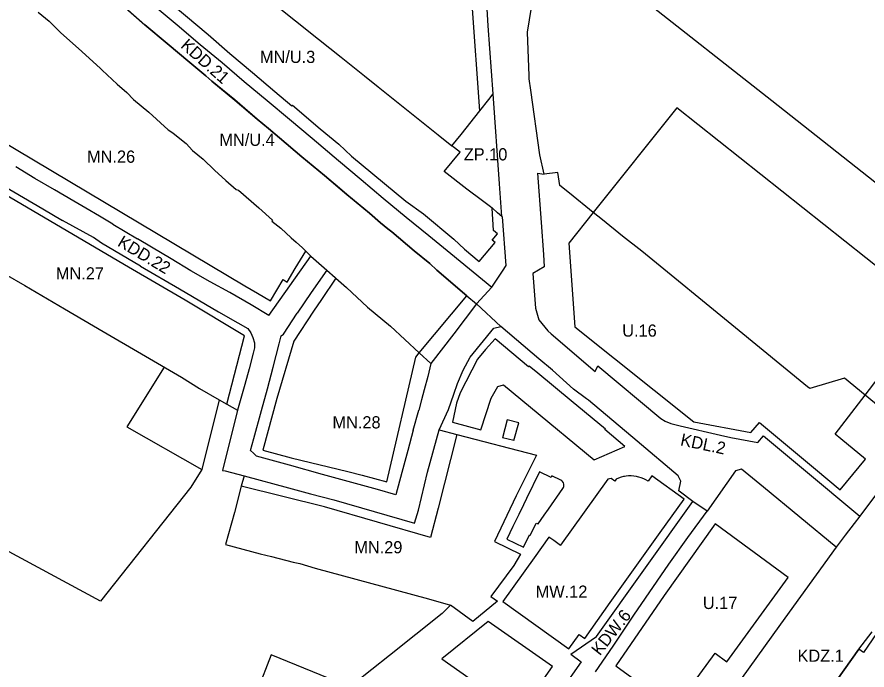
# Model space of a CAD drawing. Extents: x 7425067 to 7426806, y 5549054 to 5550619.
# Drawn here: x 7426010.9 to 7426359, y 5549627.2 to 5549894.6 of the extents above; entities that cross this region are included whole.
import ezdxf

# ---------------------------------------------------------------- set-up
doc = ezdxf.new("R2010")
doc.units = 0
for name, color, linetype in [('LIN_Linia Zabudowy Nieprzekraczalna', 7, 'Continuous'), ('LIN_linia zabudowy obowiązująca', 7, 'Continuous'), ('LIN_linie_rozgraniczajace', 7, 'Continuous'), ('TXT_Oznaczenia_przeznaczen', 7, 'Continuous')]:
    doc.layers.add(name, color=color, linetype=linetype)

msp = doc.modelspace()

# ---------------------------------------------------------------- linework, layer by layer
at = {"layer": 'LIN_Linia Zabudowy Nieprzekraczalna'}
for points in [[(7426200.381, 5549856.1483), (7426197.2527, 5549899.9387)], [(7425985.5251, 5549854.844), (7425996.26, 5549848.76), (7426104.12, 5549784.6), (7426109.41, 5549781.49), (7426114.72, 5549778.36), (7426119.83, 5549787.08), (7426121.57, 5549786.02), (7426124.86, 5549791.65), (7426129.1728, 5549798.7414)], [(7426104.0355, 5549764.0477), (7426079.76, 5549778.72), (7426056.48, 5549792.16), (7426008.48, 5549820.45), (7425975.3407, 5549839.5758)], [(7426200.17, 5549794.45), (7426206.73, 5549802.26), (7426205.5, 5549803.28), (7426207.65, 5549805.84), (7426206.0238, 5549807.2008), (7426205.4248, 5549816.3958)], [(7426129.1728, 5549798.7414), (7426131.18, 5549796.71), (7426136.68, 5549791.87), (7426137.71, 5549790.96), (7426141.23, 5549787.89), (7426141.5092, 5549787.6438), (7426135.63, 5549779), (7426132.35, 5549774.1), (7426124.1921, 5549761.9129)], [(7426096.874, 5549736.0834), (7426104.0355, 5549764.0477)], [(7426124.1921, 5549761.9129), (7426117.32, 5549738.38), (7426111.5641, 5549717.2208)], [(7426162.3022, 5549704.3065), (7426174.1872, 5549755.359), (7426175.6236, 5549757.0814)], [(7426071.1409, 5549751.2426), (7426055.9087, 5549726.8223), (7426086.61, 5549709.3037)], [(7426191.0178, 5549723.619), (7426183.33, 5549693.47), (7426180.274, 5549681.4855)], [(7426111.5641, 5549717.2208), (7426123.12, 5549714.13), (7426146.34, 5549708.54), (7426152.21, 5549706.94), (7426162.3022, 5549704.3065)], [(7426284.14, 5549697.19), (7426270.93, 5549706.67), (7426269.39, 5549704.52), (7426268.48, 5549705.06), (7426267.54, 5549705.53), (7426266.56, 5549705.92), (7426265.55, 5549706.23), (7426265.07, 5549706.35), (7426264.53, 5549706.46), (7426263.48, 5549706.62), (7426262.46, 5549706.69), (7426261.38, 5549706.67), (7426260.33, 5549706.57), (7426259.63, 5549706.46), (7426259.29, 5549706.4), (7426258.27, 5549706.14), (7426257.27, 5549705.8), (7426256.3, 5549705.38), (7426255.74, 5549704.59), (7426254.24, 5549705.67), (7426252.85, 5549705.41), (7426233.49, 5549678.3), (7426233.46, 5549678.26), (7426230.77, 5549680.19), (7426228.74, 5549681.63), (7426222.64, 5549673.08), (7426209.91, 5549655.22), (7426236.92, 5549635.84), (7426241.17, 5549641.77), (7426243.41, 5549640.17), (7426253.86, 5549654.81), (7426274.35, 5549683.48), (7426284.14, 5549697.19)], [(7426136.83, 5549694.02), (7426102.7507, 5549702.5468)], [(7426180.274, 5549681.4855), (7426136.83, 5549694.02)], [(7426296.746, 5549687.118), (7426275.9371, 5549657.7273)], [(7426326.69, 5549665.13), (7426296.746, 5549687.118)], [(7426275.9371, 5549657.7273), (7426256.0787, 5549628.8601)], [(7426370.03, 5549652.54), (7426362.92, 5549642.18), (7426357.542, 5549634.3437)], [(7426357.542, 5549634.3437), (7426355.61, 5549635.73), (7426346.69, 5549623.04), (7426339.9401, 5549613.4599)], [(7426256.0787, 5549628.8601), (7426270.22, 5549618.64), (7426280.1535, 5549611.3656)]]:
    msp.add_lwpolyline(points, dxfattribs=at)
at = {"layer": 'LIN_linia zabudowy obowiązująca'}
for points in [[(7426032.1248, 5549939.0592), (7426039.09, 5549932.41), (7426038.69, 5549931.97), (7426039.33, 5549931.35), (7426039.76, 5549931.8), (7426044.26, 5549927.62), (7426043.79, 5549927.11), (7426044.09, 5549926.83), (7426044.26, 5549926.99), (7426053.09, 5549918.46), (7426061.82, 5549910.73), (7426071.03, 5549902.74), (7426079.84, 5549895.27), (7426089.14, 5549887.45), (7426098.08, 5549879.64), (7426107.28, 5549871.91), (7426116.5, 5549864.05), (7426123.48, 5549858.2)], [(7426265.8603, 5549903.2149), (7426320, 5549860.43), (7426369.9917, 5549820.9231), (7426401.5017, 5549796.0217)], [(7426179.9175, 5549793.6725), (7426173.55, 5549798.88), (7426164.33, 5549806.59), (7426162.69, 5549807.94), (7426159.74, 5549810.37), (7426155.2, 5549814.26), (7426145.95, 5549822), (7426142.96, 5549824.47), (7426136.77, 5549829.67), (7426127.54, 5549837.39), (7426118.41, 5549845.08), (7426113.86, 5549848.94), (7426109.27, 5549852.8), (7426100.15, 5549860.68), (7426090.69, 5549868.3), (7426088.2, 5549870.51), (7426081.64, 5549876), (7426072.39, 5549883.73), (7426063.21, 5549891.38), (7426056.21, 5549897.61)], [(7426123.48, 5549858.2), (7426123.7009, 5549858.4687)], [(7426123.7009, 5549858.4687), (7426134.99, 5549848.83), (7426142.67, 5549842.49), (7426147.92, 5549837.67), (7426170.19, 5549819.18), (7426177.31, 5549813.99), (7426189.82, 5549803.71), (7426194.09, 5549799.52), (7426200.17, 5549794.45)], [(7426281.18, 5549857.47), (7426246.9144, 5549814.5236), (7426236.8895, 5549801.959)], [(7426385.0744, 5549774.9325), (7426384.36, 5549775.5), (7426281.18, 5549857.47)], [(7426236.8895, 5549801.959), (7426239.4064, 5549767.7162)], [(7426195.149, 5549780.4937), (7426182.82, 5549790.88), (7426179.9175, 5549793.6725)], [(7426175.6236, 5549757.0814), (7426195.149, 5549780.4937)], [(7426346.0059, 5549723.7436), (7426358.2546, 5549739.7922), (7426385.0744, 5549774.9325)], [(7426239.4064, 5549767.7162), (7426288.1244, 5549728.789)], [(7426189.27, 5549728.72), (7426200.83, 5549725.61), (7426205.14, 5549738.49), (7426207.78, 5549743.32), (7426210.17, 5549743.93), (7426221.15, 5549734.85), (7426247.2643, 5549713.2982), (7426259.8391, 5549718.7566), (7426251.66, 5549725.65), (7426251.85, 5549725.88), (7426237.86, 5549737.45), (7426224.14, 5549748.72), (7426220.61, 5549751.69), (7426220.34, 5549751.37), (7426206.72, 5549762.78), (7426202.7, 5549758.45), (7426199.48, 5549754.54), (7426192.42, 5549740.78), (7426190.86, 5549736.42), (7426189.27, 5549728.72)], [(7426211.6722, 5549729.6117), (7426209.7433, 5549722.3059)], [(7426214.4159, 5549721.1377), (7426216.3378, 5549728.3983), (7426211.6722, 5549729.6117)], [(7426288.1244, 5549728.789), (7426311.4587, 5549724.4299)], [(7426311.4587, 5549724.4299), (7426314.908, 5549728.5898)], [(7426314.908, 5549728.5898), (7426337.87, 5549709.47), (7426347.97, 5549701.06)], [(7426214.4159, 5549721.1377), (7426209.7433, 5549722.3059)], [(7426347.97, 5549701.06), (7426358.32, 5549713.49), (7426348.22, 5549721.9), (7426346.0059, 5549723.7436)], [(7426211.52, 5549680.83), (7426218.34, 5549677.54), (7426220.74, 5549682.5), (7426221.05, 5549682.35), (7426223.48, 5549687.39), (7426224.26, 5549687.02), (7426226.82, 5549690.68), (7426228.51, 5549693.09), (7426234.45, 5549701.6), (7426234.64, 5549701.9), (7426234.79, 5549702.27), (7426234.87, 5549702.79), (7426234.84, 5549703.33), (7426234.65, 5549703.88), (7426234.34, 5549704.35), (7426233.96, 5549704.7), (7426233.58, 5549704.93), (7426229.89, 5549706.71), (7426229.59, 5549706.08), (7426224.81, 5549708.38), (7426219.53, 5549697.43), (7426218.26, 5549694.81), (7426216.41, 5549690.96), (7426213.97, 5549685.92), (7426211.52, 5549680.83)], [(7426296.7731, 5549634.1389), (7426301.61, 5549630.62), (7426326.69, 5549665.13)], [(7426203.81, 5549647.1), (7426184.83, 5549631.79), (7426216.68, 5549609.4), (7426230.16, 5549628.58), (7426203.81, 5549647.1)], [(7426138.73, 5549623.67), (7426115.01, 5549633.36), (7426109.38, 5549619.02), (7426132.94, 5549609.78), (7426138.73, 5549623.67)], [(7426280.1535, 5549611.3656), (7426296.7731, 5549634.1389)]]:
    msp.add_lwpolyline(points, dxfattribs=at)
at = {"layer": 'LIN_linie_rozgraniczajace'}
for points in [[(7426219.97, 5549888.38), (7426222.27, 5549902.93)], [(7426115.54, 5549900.56), (7426124.99, 5549893.01)], [(7426203.9, 5549891), (7426203.24, 5549900.33)], [(7426019.55, 5549896.58), (7426024.1, 5549892.94)], [(7426054.24, 5549899.28), (7426063.21, 5549891.38)], [(7426067.43, 5549898.97), (7426076.45, 5549891.36)], [(7426024.1, 5549892.94), (7426028.66, 5549888.31)], [(7426124.99, 5549893.01), (7426134.35, 5549885.53)], [(7426063.21, 5549891.38), (7426072.39, 5549883.73)], [(7426076.45, 5549891.36), (7426085.89, 5549883.42)], [(7426205.9, 5549863.1), (7426203.9, 5549891)], [(7426028.66, 5549888.31), (7426037.47, 5549880.44)], [(7426134.35, 5549885.53), (7426138.995, 5549881.82)], [(7426220.65, 5549870.52), (7426219.97, 5549888.38)], [(7426072.39, 5549883.73), (7426081.64, 5549876)], [(7426085.89, 5549883.42), (7426094.89, 5549875.93)], [(7426037.47, 5549880.44), (7426045.02, 5549873.57)], [(7426138.995, 5549881.82), (7426143.64, 5549878.11)], [(7426081.64, 5549876), (7426088.2, 5549870.51)], [(7426094.89, 5549875.93), (7426103.93, 5549868.17)], [(7426143.64, 5549878.11), (7426148.395, 5549874.315)], [(7426045.02, 5549873.57), (7426045.81, 5549872.79)], [(7426045.81, 5549872.79), (7426051.85, 5549867.13)], [(7426148.395, 5549874.315), (7426153.15, 5549870.52)], [(7426088.2, 5549870.51), (7426090.69, 5549868.3)], [(7426090.69, 5549868.3), (7426100.16, 5549860.57)], [(7426103.93, 5549868.17), (7426113.31, 5549860.41)], [(7426153.15, 5549870.52), (7426158.735, 5549866.06)], [(7426220.7, 5549869.34), (7426220.65, 5549870.52)], [(7426221.36, 5549864.62), (7426220.7, 5549869.34)], [(7426051.85, 5549867.13), (7426055.92, 5549863.67)], [(7426158.735, 5549866.06), (7426164.32, 5549861.6)], [(7426225.06, 5549838.18), (7426221.36, 5549864.62)], [(7426055.92, 5549863.67), (7426058.66, 5549860.83)], [(7426164.32, 5549861.6), (7426169.065, 5549857.81)], [(7426195.08, 5549824.08), (7426185.76, 5549831.33), (7426192.31, 5549839.24), (7426189.03, 5549841.86), (7426192.76, 5549846.56), (7426200.381, 5549856.1483), (7426204.11, 5549860.84), (7426205.9, 5549863.1)], [(7426208.53, 5549826.28), (7426205.9, 5549863.1)], [(7426058.66, 5549860.83), (7426064.93, 5549855.6)], [(7426100.16, 5549860.57), (7426109.27, 5549852.8)], [(7426113.31, 5549860.41), (7426122.48, 5549852.76)], [(7426169.065, 5549857.81), (7426173.81, 5549854.02)], [(7426064.93, 5549855.6), (7426072.78, 5549848.45)], [(7426109.27, 5549852.8), (7426113.86, 5549848.94)], [(7426122.48, 5549852.76), (7426131.75, 5549844.96)], [(7426173.81, 5549854.02), (7426178.57, 5549850.22)], [(7426072.78, 5549848.45), (7426073.52, 5549848.03)], [(7426073.52, 5549848.03), (7426074.9, 5549847.04)], [(7426113.86, 5549848.94), (7426118.41, 5549845.08)], [(7426178.57, 5549850.22), (7426183.33, 5549846.42)], [(7426074.9, 5549847.04), (7426080.15, 5549842.78)], [(7426118.41, 5549845.08), (7426127.54, 5549837.39)], [(7426131.75, 5549844.96), (7426142.52, 5549835.89)], [(7426183.33, 5549846.42), (7426189.03, 5549841.86)], [(7426080.15, 5549842.78), (7426082.78, 5549839.92)], [(7426082.78, 5549839.92), (7426087.19, 5549836.34)], [(7426127.54, 5549837.39), (7426136.77, 5549829.67)], [(7426226.79, 5549830.23), (7426225.06, 5549838.18)], [(7426018.22, 5549828.5), (7426010.36, 5549833.25)], [(7426087.19, 5549836.34), (7426091.77, 5549831.87)], [(7426142.52, 5549835.89), (7426151.78, 5549828.03)], [(7426091.77, 5549831.87), (7426096.44, 5549827.71)], [(7426224.07, 5549830.67), (7426226.79, 5549830.23)], [(7426224.07, 5549830.67), (7426225.51, 5549810.49)], [(7426379.83, 5549722.02), (7426358.2546, 5549739.7922), (7426349.82, 5549746.74), (7426335.58, 5549742.45), (7426334.69, 5549743.18), (7426305.14, 5549767.39), (7426266.81, 5549798.71), (7426258.9, 5549804.84), (7426250.64, 5549811.51), (7426246.9144, 5549814.5236), (7426237.14, 5549822.43), (7426233.21, 5549825.6), (7426232.39, 5549830.98), (7426226.79, 5549830.23)], [(7426026.27, 5549823.84), (7426018.22, 5549828.5)], [(7426096.44, 5549827.71), (7426100.66, 5549823.95)], [(7426136.77, 5549829.67), (7426145.95, 5549822)], [(7426151.78, 5549828.03), (7426160.9, 5549820.44)], [(7426005.595, 5549825.4), (7426013.57, 5549820.77)], [(7426034.21, 5549819.21), (7426026.27, 5549823.84)], [(7426100.66, 5549823.95), (7426101.63, 5549823.73)], [(7426101.63, 5549823.73), (7426109.98, 5549816.43)], [(7426209.49, 5549812.91), (7426207.65, 5549814.49), (7426205.56, 5549816.28), (7426205.4248, 5549816.3958), (7426204.81, 5549816.91), (7426201.52, 5549819.33), (7426195.08, 5549824.08)], [(7426209.49, 5549812.91), (7426208.53, 5549826.28)], [(7426013.57, 5549820.77), (7426017.51, 5549818.435)], [(7426145.95, 5549822), (7426149, 5549819.41)], [(7426149, 5549819.41), (7426155.2, 5549814.26)], [(7426160.9, 5549820.44), (7426170.26, 5549812.65)], [(7426017.51, 5549818.435), (7426021.45, 5549816.1)], [(7426021.45, 5549816.1), (7426029.56, 5549811.31)], [(7426039.1, 5549816.3), (7426034.21, 5549819.21)], [(7426044.615, 5549813.01), (7426039.1, 5549816.3)], [(7426109.98, 5549816.43), (7426115.5, 5549811.36)], [(7426050.13, 5549809.72), (7426044.615, 5549813.01)], [(7426155.2, 5549814.26), (7426159.74, 5549810.37)], [(7426170.26, 5549812.65), (7426179.55, 5549805.18)], [(7426209.7, 5549812.79), (7426209.49, 5549812.91)], [(7426211.21, 5549792.9), (7426209.7, 5549812.79)], [(7426045.5, 5549801.98), (7426042.22, 5549804.28), (7426029.56, 5549811.31)], [(7426050.13, 5549809.72), (7426055.17, 5549806.75)], [(7426115.5, 5549811.36), (7426115.29, 5549811.01)], [(7426115.29, 5549811.01), (7426118.9, 5549808.11)], [(7426159.74, 5549810.37), (7426162.69, 5549807.94)], [(7426225.51, 5549810.49), (7426226.44, 5549797.35)], [(7426055.17, 5549806.75), (7426060.21, 5549803.78)], [(7426118.9, 5549808.11), (7426123.16, 5549804.18)], [(7426162.69, 5549807.94), (7426164.33, 5549806.59)], [(7426164.33, 5549806.59), (7426173.55, 5549798.88)], [(7426061.45, 5549792.57), (7426045.5, 5549801.98)], [(7426066.01, 5549800.37), (7426060.21, 5549803.78)], [(7426123.16, 5549804.18), (7426125.19, 5549802.45)], [(7426125.19, 5549802.45), (7426127.86, 5549800.07)], [(7426179.55, 5549805.18), (7426188.5, 5549797.73)], [(7426074.035, 5549795.545), (7426066.01, 5549800.37)], [(7426127.86, 5549800.07), (7426129.1728, 5549798.7414), (7426131.18, 5549796.71)], [(7426173.55, 5549798.88), (7426179.9175, 5549793.6725)], [(7426082.06, 5549790.72), (7426074.035, 5549795.545)], [(7426114.04, 5549772.41), (7426131.18, 5549796.71)], [(7426131.18, 5549796.71), (7426136.68, 5549791.87)], [(7426188.5, 5549797.73), (7426205.3, 5549783.93)], [(7426226.44, 5549797.35), (7426226.78, 5549792.36)], [(7426061.45, 5549792.57), (7426077.4, 5549783.31)], [(7426136.68, 5549791.87), (7426137.71, 5549790.96)], [(7426179.9175, 5549793.6725), (7426182.82, 5549790.88)], [(7426209.78, 5549790.51), (7426211.21, 5549792.9)], [(7426226.78, 5549792.36), (7426222.1808, 5549789.6332)], [(7426005.99, 5549789.25), (7426014.04, 5549784.65)], [(7426090.035, 5549786.235), (7426082.06, 5549790.72)], [(7426137.71, 5549790.96), (7426131.3, 5549781.84)], [(7426137.71, 5549790.96), (7426141.23, 5549787.89)], [(7426182.82, 5549790.88), (7426195.149, 5549780.4937), (7426199.13, 5549777.14)], [(7426207.54, 5549787.22), (7426209.78, 5549790.51)], [(7426222.1808, 5549789.6332), (7426223.2149, 5549775.359)], [(7426014.04, 5549784.65), (7426030.36, 5549775.11)], [(7426098.01, 5549781.75), (7426090.035, 5549786.235)], [(7426141.23, 5549787.89), (7426141.5092, 5549787.6438), (7426145.79, 5549783.87)], [(7426205.3, 5549783.93), (7426207.54, 5549787.22)], [(7426077.4, 5549783.31), (7426093.46, 5549773.92)], [(7426106.81, 5549776.79), (7426098.01, 5549781.75)], [(7426131.3, 5549781.84), (7426125.65, 5549773.36)], [(7426145.79, 5549783.87), (7426154.47, 5549775.82)], [(7426199.13, 5549777.14), (7426205.3, 5549783.93)], [(7426030.36, 5549775.11), (7426046.15, 5549765.84)], [(7426114.04, 5549772.41), (7426106.81, 5549776.79)], [(7426154.47, 5549775.82), (7426163.78, 5549768.08)], [(7426199.13, 5549777.14), (7426189.725, 5549764.93)], [(7426208.98, 5549767.82), (7426199.13, 5549777.14)], [(7426223.2149, 5549775.359), (7426224.5923, 5549770.6262)], [(7426093.46, 5549773.92), (7426101.3, 5549769.39)], [(7426120.06, 5549764.71), (7426125.65, 5549773.36)], [(7426224.5923, 5549770.6262), (7426228.27, 5549766.0998)], [(7426101.3, 5549769.39), (7426105.39, 5549767.07)], [(7426163.78, 5549768.08), (7426175.6236, 5549757.0814), (7426180.32, 5549752.72)], [(7426196.51, 5549755.34), (7426206.2, 5549767.14)], [(7426206.2, 5549767.14), (7426208.98, 5549767.82)], [(7426224.6, 5549754.7), (7426208.98, 5549767.82)], [(7426046.15, 5549765.84), (7426061.86, 5549756.7)], [(7426105.39, 5549767.07), (7426106.6, 5549765.32)], [(7426106.6, 5549765.32), (7426107.49, 5549763.39)], [(7426118.26, 5549760.84), (7426119.05, 5549764.05)], [(7426119.05, 5549764.05), (7426120.06, 5549764.71)], [(7426189.725, 5549764.93), (7426180.32, 5549752.72)], [(7426228.27, 5549766.0998), (7426229.6949, 5549764.8724)], [(7426229.6949, 5549764.8724), (7426247.7057, 5549749.3939)], [(7426107.49, 5549763.39), (7426108.16, 5549761.21)], [(7426108.125, 5549760.145), (7426108.09, 5549759.08)], [(7426108.16, 5549761.21), (7426108.125, 5549760.145)], [(7426115.8, 5549751.18), (7426118.26, 5549760.84)], [(7426061.86, 5549756.7), (7426078.22, 5549747.08)], [(7426107.61, 5549757.01), (7426105.895, 5549750.57)], [(7426108.09, 5549759.08), (7426107.61, 5549757.01)], [(7426193.6632, 5549750.037), (7426196.51, 5549755.34)], [(7426230.21, 5549749.98), (7426224.6, 5549754.7)], [(7426105.895, 5549750.57), (7426104.18, 5549744.13)], [(7426113.42, 5549742.32), (7426115.8, 5549751.18)], [(7426180.32, 5549752.72), (7426179.07, 5549747.4)], [(7426191.33, 5549744.52), (7426193.6632, 5549750.037)], [(7426238.81, 5549742.28), (7426230.21, 5549749.98)], [(7426247.7057, 5549749.3939), (7426248.76, 5549751.71)], [(7426248.76, 5549751.71), (7426274.53, 5549730.17)], [(7426078.22, 5549747.08), (7426085.61, 5549742.52)], [(7426179.07, 5549747.4), (7426177.63, 5549741.92)], [(7426104.18, 5549744.13), (7426101.15, 5549733.64)], [(7426189.785, 5549740.105), (7426191.33, 5549744.52)], [(7426085.61, 5549742.52), (7426093.7325, 5549737.8786), (7426096.874, 5549736.0834), (7426101.15, 5549733.64)], [(7426111.04, 5549733.46), (7426113.42, 5549742.32)], [(7426177.63, 5549741.92), (7426176.535, 5549737.8)], [(7426187.61, 5549733.84), (7426189.785, 5549740.105)], [(7426244.1, 5549738.28), (7426238.81, 5549742.28)], [(7426093.7325, 5549737.8786), (7426086.61, 5549709.3037)], [(7426176.535, 5549737.8), (7426175.44, 5549733.68)], [(7426244.91, 5549737.66), (7426244.1, 5549738.28)], [(7426264.8, 5549720.91), (7426244.91, 5549737.66)], [(7426101.15, 5549733.64), (7426095.09, 5549708.97)], [(7426107.89, 5549722.05), (7426111.04, 5549733.46)], [(7426173.165, 5549725.415), (7426175.44, 5549733.68)], [(7426183.71, 5549725.5), (7426187.61, 5549733.84)], [(7426274.53, 5549730.17), (7426276.32, 5549729.05)], [(7426276.32, 5549729.05), (7426278.64, 5549728.19)], [(7426173.165, 5549725.415), (7426170.89, 5549717.15)], [(7426178.99, 5549708.17), (7426183.71, 5549725.5)], [(7426183.71, 5549725.5), (7426191.0178, 5549723.619), (7426223.61, 5549715.23)], [(7426278.64, 5549728.19), (7426282.51, 5549727.18)], [(7426282.51, 5549727.18), (7426298.99, 5549723.39)], [(7426107.215, 5549719.6), (7426107.89, 5549722.05)], [(7426298.99, 5549723.39), (7426303.21, 5549722.39)], [(7426303.21, 5549722.39), (7426314.25, 5549720.36)], [(7426314.25, 5549720.36), (7426316.5887, 5549723.125)], [(7426316.5887, 5549723.125), (7426333.0237, 5549709.4303)], [(7426106.54, 5549717.15), (7426107.215, 5549719.6)], [(7426281.6, 5549706.76), (7426264.8, 5549720.91)], [(7426107.78, 5549715.99), (7426106.54, 5549717.15)], [(7426109.02, 5549714.83), (7426107.78, 5549715.99)], [(7426170.89, 5549717.15), (7426168.445, 5549708.08)], [(7426223.61, 5549715.23), (7426215.32, 5549698.49)], [(7426122.5, 5549711.085), (7426109.02, 5549714.83)], [(7426086.61, 5549709.3037), (7426082.1086, 5549702.1142)], [(7426095.09, 5549708.97), (7426096.12, 5549708.8)], [(7426096.12, 5549708.8), (7426103.87, 5549706.73)], [(7426135.98, 5549707.34), (7426122.5, 5549711.085)], [(7426168.445, 5549708.08), (7426166, 5549699.01)], [(7426175.25, 5549692.71), (7426178.99, 5549708.17)], [(7426305.18, 5549708.79), (7426293.56, 5549692.23)], [(7426307.6, 5549709.48), (7426305.18, 5549708.79)], [(7426316.6151, 5549702.0353), (7426307.6, 5549709.48)], [(7426333.0237, 5549709.4303), (7426356.03, 5549690.26)], [(7426103.87, 5549706.73), (7426102.7507, 5549702.5468), (7426099.9, 5549691.72)], [(7426103.87, 5549706.73), (7426122.13, 5549701.83)], [(7426143.51, 5549705.265), (7426135.98, 5549707.34)], [(7426151.04, 5549703.19), (7426143.51, 5549705.265)], [(7426282.76, 5549704.55), (7426281.6, 5549706.76)], [(7426281.88, 5549700.57), (7426282.76, 5549704.55)], [(7426082.1086, 5549702.1142), (7426045.0272, 5549655.3976)], [(7426122.13, 5549701.83), (7426131.11, 5549699.42)], [(7426158.52, 5549701.1), (7426151.04, 5549703.19)], [(7426166, 5549699.01), (7426158.52, 5549701.1)], [(7426346.35, 5549677.48), (7426316.6151, 5549702.0353)], [(7426364.545, 5549701.505), (7426356.03, 5549690.26)], [(7426131.11, 5549699.42), (7426140.57, 5549696.86)], [(7426215.32, 5549698.49), (7426206.45, 5549679.87)], [(7426282.09, 5549700.41), (7426281.88, 5549700.57)], [(7426287.73, 5549696.28), (7426282.09, 5549700.41)], [(7426045.0272, 5549655.3976), (7425973.3638, 5549694.0133)], [(7426140.57, 5549696.86), (7426173.67, 5549687.31)], [(7426248.18, 5549640.9), (7426287.73, 5549696.28)], [(7426293.56, 5549692.23), (7426287.73, 5549696.28)], [(7426099.9, 5549691.72), (7426096.33, 5549678.55)], [(7426173.67, 5549687.31), (7426175.25, 5549692.71)], [(7426285.68, 5549681.425), (7426293.56, 5549692.23)], [(7426353.75, 5549687.25), (7426350.05, 5549682.365)], [(7426356.03, 5549690.26), (7426353.75, 5549687.25)], [(7426277.8, 5549670.62), (7426285.68, 5549681.425)], [(7426350.05, 5549682.365), (7426346.35, 5549677.48)], [(7426096.33, 5549678.55), (7426110.52, 5549674.76)], [(7426206.45, 5549679.87), (7426217.1, 5549674.66), (7426214.36, 5549670.06), (7426204.96, 5549657.3), (7426207.69, 5549655.46), (7426197.54, 5549647.07), (7426188.36, 5549653.81)], [(7426346.35, 5549677.48), (7426323.635, 5549645.995)], [(7426110.52, 5549674.76), (7426115.17, 5549673.64)], [(7426115.17, 5549673.64), (7426124.01, 5549671.4)], [(7426124.01, 5549671.4), (7426126.78, 5549670.81)], [(7426126.78, 5549670.81), (7426132.99, 5549668.98)], [(7426263.535, 5549649.615), (7426277.8, 5549670.62)], [(7426132.99, 5549668.98), (7426166.29, 5549659.88)], [(7426166.29, 5549659.88), (7426179.37, 5549656.31)], [(7426179.37, 5549656.31), (7426188.36, 5549653.81)], [(7426188.36, 5549653.81), (7426184.99, 5549650.38)], [(7426184.99, 5549650.38), (7426163.385, 5549633.14)], [(7426258.63, 5549642.3), (7426263.535, 5549649.615)], [(7426323.635, 5549645.995), (7426300.92, 5549614.51)], [(7426254.995, 5549637.01), (7426258.63, 5549642.3)], [(7426355.61, 5549635.73), (7426361.05, 5549642.83)], [(7426237.67, 5549633.73), (7426248.18, 5549640.9)], [(7426247.76, 5549626.42), (7426254.995, 5549637.01)], [(7426346.69, 5549623.04), (7426355.61, 5549635.73)], [(7426163.385, 5549633.14), (7426141.78, 5549615.9)], [(7426237.67, 5549633.73), (7426242, 5549630.59)], [(7426242, 5549630.59), (7426217.83, 5549596.2)]]:
    msp.add_lwpolyline(points, dxfattribs=at)

# ---------------------------------------------------------------- texts
at = {"layer": 'TXT_Oznaczenia_przeznaczen'}
for s, rotation, p in [('KDD.21', 318.372618, (7426077.5857, 5549882.4147)), ('KDD.22', 329.103837, (7426051.6984, 5549801.1422)), ('KDL.2', 348.047521, (7426282.2918, 5549719.2705)), ('KDW.6', 51.742975, (7426249.5872, 5549632.7976))]:
    msp.add_text(s, height=5, rotation=rotation, dxfattribs=at).set_placement(p)
for s, p in [('MN/U.3', (7426110.3693, 5549875.7882)), ('MN/U.4', (7426093.7723, 5549841.8572)), ('ZP.10', (7426193.858, 5549835.8937)), ('MN.26', (7426039.5683, 5549834.944)), ('MN.27', (7426026.7977, 5549787.1388)), ('U.16', (7426258.7518, 5549763.7163)), ('MN.28', (7426140.0847, 5549726.1459)), ('MN.29', (7426149.0258, 5549674.9957)), ('MW.12', (7426223.2934, 5549656.8032)), ('U.17', (7426291.769, 5549652.1787)), ('KDZ.1', (7426330.5451, 5549630.5604))]:
    msp.add_text(s, height=5, dxfattribs=at).set_placement(p)

doc.saveas('drawing.dxf')
